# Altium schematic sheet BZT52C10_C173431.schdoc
size 127 x 101 mm
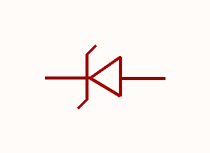
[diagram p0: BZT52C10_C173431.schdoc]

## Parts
D?  bzt52c10_c173431  [SOD-123_L2.8-W1.8-LS3.7-RD]  (value not drawn)

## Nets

Not connected (* = marked no-connect by the designer): D? 1(K) 2(A)

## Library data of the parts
D? = bzt52c10_c173431: 二极管配置:1个独立式;稳压值(标称值):10V;稳压值(范围):9.5V~10.5V;耗散功率(Pd):500mW;; Manufacturer: MDD(辰达半导体); AddInBom: yes; ModelId: 7884390a25fb4c08947731ebfba7e3f8; ModelTransform: 144.8816,62.992,0,0,0,0,0,0,0; Diode Configuration: 1个独立式; Zener Voltage(Nom): 10V; Reverse Leakage Current (Ir): 100nA@7V; Pd - Power Dissipation: 500mW; Impedance(Zzt): 30Ω; Tolerance: ±5%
